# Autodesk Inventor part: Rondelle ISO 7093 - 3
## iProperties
Created: 2011-01
Part Number: Rondelle ISO 7093 - 3
Document SubType Name: Modeling
Designer: eric
Density: 1 g/cm^3
Mass: 0.0243536 g
Surface Area: 0.865195 cm^2
Volume: 0.0243536 cm^3
Author: eric
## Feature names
1. Base1
